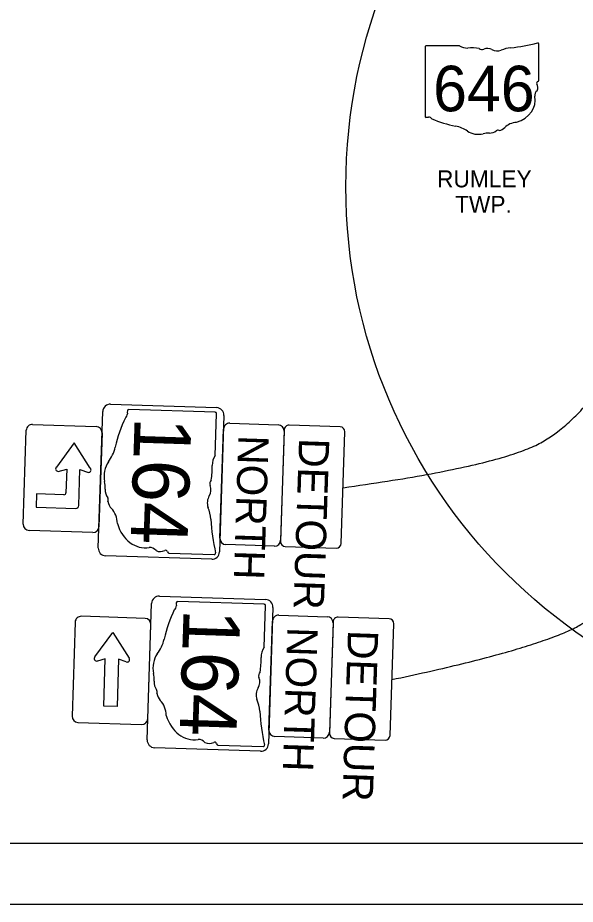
# Model space of a CAD drawing. Extents: x -740 to 1519, y 0 to 440.
# Drawn here: x 350.9 to 442.8, y 0 to 146.1 of the extents above; entities that cross this region are included whole.
import ezdxf

# ---------------------------------------------------------------- set-up
doc = ezdxf.new("R2010")
doc.units = 0
for name, color, linetype in [('GM_X_County_Road_Text', 7, 'Continuous'), ('GM_X_Minor_Lake', 7, 'Continuous'), ('GM_X_Minor_River', 7, 'Continuous'), ('GM_X_Section', 7, 'Continuous'), ('SH_Border', 7, 'Continuous'), ('SH_Cut_Line', 7, 'Continuous'), ('SH_Data', 7, 'Continuous')]:
    doc.layers.add(name, color=color, linetype=linetype)

msp = doc.modelspace()

# ---------------------------------------------------------------- linework, layer by layer
at = {"layer": 'GM_X_County_Road_Text'}
for p, q in [((436.81, 135.77), (436.81, 141.72)), ((418.07, 141.24), (418.07, 129.86)), ((423.74, 141.44), (418.25, 141.44)), ((436.81, 135.77), (436.81, 135.77))]:
    msp.add_line(p, q, dxfattribs=at)
for centre, major_axis, start_param, end_param in [((430.14, 156.96), (19.88, 0), 4.814394, 5.042369), ((436.61, 141.75), (0.209, 0), 6.141152, 7.989035), ((418.28, 141.27), (0.217, 0), 1.712693, 3.28349), ((425.05, 142.76), (2.11, 0), 4.042523, 4.731795), ((425.75, 135.05), (7.56, 0), 1.404758, 1.657858), ((427.46, 141.33), (0.608, 0), 3.836095, 5.185415), ((428.36, 140.01), (1.26, 0), 0.950623, 2.079405), ((429.99, 141.82), (1.52, 0), 4.081561, 5.145723), ((432.67, 137.96), (4, 0), 1.699011, 2.107814), ((436.77, 135.33), (0.323, 0), 1.883978, 3.671073), ((434.71, 134.58), (1.94, 0), 5.934695, 6.695948), ((436.59, 135.74), (0.223, 0), 5.05454, 6.418171), ((431.25, 132.52), (4.97, 0), 5.101752, 6.440018), ((437.56, 133.27), (1.41, 0), 2.387724, 3.262537), ((418.28, 129.83), (0.219, 0), 3.00124, 4.508301), ((418.32, 131), (1.67, 0), 4.665946, 4.897461), ((418.66, 129.2), (0.603, 0), 0.519207, 1.627899), ((426.27, 139.43), (14.36, 0), 4.195997, 4.488961), ((433.35, 126.66), (2.72, 0), 1.647645, 2.488434), ((421.99, 124.75), (4.49, 0), 0.823519, 1.323587), ((426.85, 129.15), (2.85, 0), 4.026481, 4.996735), ((428.5, 125.21), (2.34, 0), 1.495662, 1.94098), ((428.7, 128.29), (1.52, 0), 4.691044, 5.507374), ((430.08, 127.19), (0.428, 0), 1.147584, 2.315152), ((429.9, 128.76), (1.61, 0), 4.937069, 5.64225)]:
    msp.add_ellipse(centre, major_axis=major_axis, ratio=0.8, start_param=start_param, end_param=end_param, dxfattribs=at)
at = {"layer": 'GM_X_Minor_Lake'}
for p, q in [((371.9, 47.1), (361.41, 47.45)), ((360.37, 46.48), (359.87, 30.99)), ((372.36, 30.58), (372.87, 46.07)), ((363.64, 40.79), (366.57, 44.78)), ((366.57, 44.78), (369.28, 40.55)), ((365.33, 40.44), (364.04, 40.08)), ((365.08, 32.63), (365.33, 40.44)), ((367.52, 40.37), (367.27, 32.56)), ((368.79, 39.93), (367.52, 40.37)), ((367.27, 32.56), (365.08, 32.63)), ((360.83, 29.96), (371.33, 29.61))]:
    msp.add_line(p, q, dxfattribs=at)
for centre, radius, start, end in [((361.37, 46.45), 1, 88.1288, 178.1288), ((371.87, 46.1), 1, 358.1288, 88.1288), ((363.93, 40.49), 0.417, 133.1192, 285.3334), ((368.93, 40.32), 0.417, 250.9242, 32.7175), ((360.87, 30.96), 1, 178.1288, 268.1288), ((371.36, 30.61), 1, 268.1288, 358.1288)]:
    msp.add_arc(centre, radius, start, end, dxfattribs=at)
at = {"layer": 'GM_X_Minor_River'}
for p, q in [((383.45, 81.06), (369.23, 81.52)), ((383.46, 73.96), (383.69, 80.82)), ((353.34, 79.07), (363.83, 78.73)), ((385.86, 79.26), (393.86, 79)), ((351.8, 62.61), (352.31, 78.1)), ((364.8, 77.7), (364.3, 62.2)), ((384.24, 60.3), (384.83, 78.29)), ((394.83, 77.97), (394.24, 59.98)), ((360.21, 76.03), (357.29, 72.04)), ((362.87, 71.86), (360.21, 76.03)), ((357.56, 71.32), (358.98, 71.69)), ((358.98, 71.69), (358.85, 67.79)), ((360.97, 65.69), (361.16, 71.62)), ((361.16, 71.62), (362.56, 71.16)), ((354, 67.64), (353.93, 65.45)), ((358.53, 67.49), (354, 67.64)), ((353.93, 65.45), (360.49, 65.23)), ((360.97, 65.69), (360.97, 65.69)), ((363.26, 61.24), (352.77, 61.58)), ((393.21, 59.01), (385.21, 59.27)), ((375.84, 57.86), (383.28, 57.61)), ((375.84, 57.86), (375.84, 57.86)), ((391.51, 49.43), (377.29, 49.9)), ((391.53, 42.34), (391.75, 49.2)), ((393.93, 47.64), (401.92, 47.37)), ((392.31, 28.68), (392.9, 46.67)), ((402.89, 46.34), (402.3, 28.35)), ((401.27, 27.39), (393.28, 27.65)), ((383.91, 26.24), (383.91, 26.23)), ((383.91, 26.23), (391.35, 25.99))]:
    msp.add_line(p, q, dxfattribs=at)
for points in [[(366.21, 82.4), (383.7, 81.83)], [(364.18, 58.71), (364.92, 81.19)], [(384.91, 80.54), (384.17, 58.05)], [(404.05, 78.66), (395.66, 78.94)], [(394.83, 78.17), (394.23, 59.78)], [(404.23, 59.45), (404.83, 77.84)], [(395.01, 58.95), (403.4, 58.68)], [(382.88, 56.84), (365.39, 57.42)], [(374.27, 50.78), (391.76, 50.21)], [(372.25, 27.08), (372.98, 49.57)], [(392.97, 48.92), (392.24, 26.43)], [(412.12, 47.04), (403.72, 47.32)], [(402.9, 46.54), (402.3, 28.15)], [(412.29, 27.83), (412.89, 46.22)], [(403.07, 27.33), (411.47, 27.05)], [(390.95, 25.22), (373.45, 25.79)]]:
    msp.add_lwpolyline(points, dxfattribs=at)
for centre, radius, start, end in [((366.17, 81.15), 1.25, 88.1288, 178.1288), ((383.66, 80.58), 1.25, 358.1288, 88.1288), ((353.31, 78.07), 1, 88.1288, 178.1288), ((385.83, 78.26), 1, 88.1288, 178.1288), ((393.83, 78), 1, 358.1288, 88.1288), ((395.63, 78.14), 0.8, 88.1288, 178.1288), ((363.8, 77.73), 1, 358.1288, 88.1288), ((404.03, 77.87), 0.8, 358.1288, 88.1288), ((357.57, 71.74), 0.417, 133.1289, 268.1304), ((362.57, 71.58), 0.417, 268.1304, 43.1286), ((358.54, 67.8), 0.312, 268.1288, 358.1288), ((360.5, 65.7), 0.469, 268.1288, 358.1288), ((352.8, 62.58), 1, 178.1288, 268.1288), ((363.3, 62.24), 1, 268.1288, 358.1288), ((385.24, 60.27), 1, 178.1288, 268.1288), ((393.24, 60.01), 1, 268.1288, 358.1288), ((365.43, 58.66), 1.25, 178.1288, 268.1288), ((395.03, 59.75), 0.8, 178.1288, 268.1288), ((403.43, 59.48), 0.8, 268.1288, 358.1288), ((382.92, 58.09), 1.25, 268.1288, 358.1288), ((374.23, 49.53), 1.25, 88.1288, 178.1288), ((391.72, 48.96), 1.25, 358.1288, 88.1288), ((393.9, 46.64), 1, 88.1288, 178.1288), ((401.89, 46.38), 1, 358.1288, 88.1288), ((403.7, 46.52), 0.8, 88.1288, 178.1288), ((412.09, 46.24), 0.8, 358.1288, 88.1288), ((393.31, 28.65), 1, 178.1288, 268.1288), ((401.3, 28.38), 1, 268.1288, 358.1288), ((403.1, 28.13), 0.8, 178.1288, 268.1288), ((411.49, 27.85), 0.8, 268.1288, 358.1288), ((373.5, 27.04), 1.25, 178.1288, 268.1288), ((390.99, 26.47), 1.25, 268.1288, 358.1288)]:
    msp.add_arc(centre, radius, start, end, dxfattribs=at)
for centre, major_axis, start_param, end_param in [((368.38, 80.81), (-0.025, -0.753), 0.519207, 1.627899), ((370.64, 81.16), (-0.07, -2.09), 4.665946, 4.897461), ((369.19, 81.25), (-0.009, -0.274), 3.00124, 4.508301), ((383.47, 80.79), (-0.009, -0.271), 1.712693, 3.28349), ((380.85, 70.88), (-0.59, -17.94), 4.195997, 4.488961), ((362.68, 76.83), (-0.18, -5.61), 0.823519, 1.323587), ((385.06, 72.27), (-0.09, -2.63), 4.042523, 4.731795), ((367.98, 70.58), (-0.12, -3.56), 4.026481, 4.996735), ((375.4, 71.71), (-0.31, -9.45), 1.404758, 1.657858), ((362.99, 68.68), (-0.1, -2.93), 1.495662, 1.94098), ((381.49, 68.25), (-0.05, -1.58), 0.950623, 2.079405), ((383.17, 69.31), (-0.025, -0.759), 3.836095, 5.185415), ((366.84, 68.29), (-0.06, -1.9), 4.691044, 5.507374), ((383.68, 66.14), (-0.06, -1.9), 4.081561, 5.145723), ((365.4, 66.62), (-0.017, -0.534), 1.147584, 2.315152), ((367.36, 66.79), (-0.07, -2.01), 4.937069, 5.64225), ((364.61, 62.56), (-0.11, -3.4), 1.647645, 2.488434), ((378.75, 62.94), (-0.16, -5), 1.699011, 2.107814), ((402.59, 65.34), (-0.81, -24.84), 4.814394, 5.042369), ((372.01, 64.94), (-0.2, -6.21), 5.101752, 6.440018), ((372.7, 57.02), (-0.06, -1.76), 2.387724, 3.262537), ((374.44, 60.53), (-0.08, -2.42), 5.934695, 6.695948), ((375.3, 57.93), (-0.013, -0.404), 1.883978, 3.671073), ((375.82, 58.14), (-0.009, -0.279), 5.05454, 6.418171), ((383.32, 57.87), (-0.009, -0.261), 6.141152, 7.989035), ((378.71, 49.54), (-0.07, -2.09), 4.665946, 4.897461), ((377.25, 49.63), (-0.009, -0.274), 3.00124, 4.508301), ((388.91, 39.26), (-0.59, -17.94), 4.195997, 4.488961), ((376.45, 49.19), (-0.025, -0.753), 0.519207, 1.627899), ((391.54, 49.16), (-0.009, -0.271), 1.712693, 3.28349), ((370.74, 45.2), (-0.18, -5.61), 0.823519, 1.323587), ((376.04, 38.95), (-0.12, -3.56), 4.026481, 4.996735), ((393.13, 40.65), (-0.09, -2.63), 4.042523, 4.731795), ((383.46, 40.09), (-0.31, -9.45), 1.404758, 1.657858), ((371.06, 37.06), (-0.1, -2.93), 1.495662, 1.94098), ((391.23, 37.69), (-0.025, -0.759), 3.836095, 5.185415), ((374.9, 36.67), (-0.06, -1.9), 4.691044, 5.507374), ((389.55, 36.63), (-0.05, -1.58), 0.950623, 2.079405), ((373.47, 35), (-0.017, -0.534), 1.147584, 2.315152), ((391.74, 34.52), (-0.06, -1.9), 4.081561, 5.145723), ((375.43, 35.16), (-0.07, -2.01), 4.937069, 5.64225), ((386.82, 31.32), (-0.16, -5), 1.699011, 2.107814), ((372.67, 30.94), (-0.11, -3.4), 1.647645, 2.488434), ((380.07, 33.32), (-0.2, -6.21), 5.101752, 6.440018), ((410.66, 33.71), (-0.81, -24.84), 4.814394, 5.042369), ((380.76, 25.4), (-0.06, -1.76), 2.387724, 3.262537), ((382.51, 28.91), (-0.08, -2.42), 5.934695, 6.695948), ((383.36, 26.31), (-0.013, -0.404), 1.883978, 3.671073), ((383.89, 26.51), (-0.009, -0.279), 5.05454, 6.418171), ((391.39, 26.25), (-0.009, -0.261), 6.141152, 7.989035)]:
    msp.add_ellipse(centre, major_axis=major_axis, ratio=0.8, start_param=start_param, end_param=end_param, dxfattribs=at)
at = {"layer": 'SH_Border'}
msp.add_lwpolyline([(30, 430), (670, 430), (670, 10), (30, 10)], close=True, dxfattribs=at)
at = {"layer": 'SH_Cut_Line'}
msp.add_lwpolyline([(0, 0), (680, 0), (680, 440), (0, 440)], close=True, dxfattribs=at)
at = {"layer": 'SH_Data'}
msp.add_circle((495, 118.25), 90, dxfattribs=at)
for points in [[(411.48, 171.47), (430.14, 170.68), (446.41, 165.94), (458.91, 157.74), (473.99, 149.23), (486.6, 132.73), (491.89, 128.22)], [(404.53, 68.64), (430.67, 72.26), (444.24, 80.18), (454.42, 98.1), (465.55, 120.36), (474.97, 127.16), (487.1, 125.36)], [(412.59, 37.02), (434.93, 41.72), (450.39, 49.27), (457.55, 80.58), (470.56, 102.28), (481.87, 117.18), (486.84, 120.55), (491.87, 123.59)]]:
    msp.add_open_spline(points, degree=2, dxfattribs=at)

# ---------------------------------------------------------------- texts
at = {"layer": 'GM_X_County_Road_Text'}
msp.add_text('646', height=7.5, dxfattribs=at).set_placement((419.39, 130.66))
at = {"layer": 'GM_X_Minor_River'}
for s, height, p in [('164', 9.375, (370.19, 80.34)), ('NORTH', 5, (387.3, 77.34)), ('DETOUR', 5, (397.29, 76.85)), ('164', 9.375, (378.26, 48.72)), ('NORTH', 5, (395.37, 45.72)), ('DETOUR', 5, (405.36, 45.23))]:
    msp.add_text(s, height=height, rotation=268.1288, dxfattribs=at).set_placement(p)
at = {"layer": 'GM_X_Section'}
for s, p in [('RUMLEY ', (420.03, 118.13)), ('TWP.', (423, 113.93))]:
    msp.add_text(s, height=2.8, dxfattribs=at).set_placement(p)

doc.saveas('drawing.dxf')
